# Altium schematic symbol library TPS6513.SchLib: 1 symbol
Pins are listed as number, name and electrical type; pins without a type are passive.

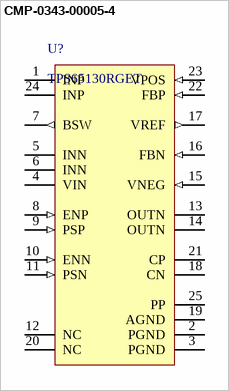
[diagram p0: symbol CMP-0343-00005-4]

## CMP-0343-00005-4
designator U?, comment TPS65130RGET
Boost Inverting Buck-Boost Voltage Converter with 2.7 to 5.5 V Input and -15 to 15 V Output, -40 to 85 degC, 24-Pin VQFN (RGE), Green (RoHS & no Sb/Br); Manufacturer: Texas Instruments; Vout2(V): -15 to -2; Regulated Outputs(#): 2; Vin(Max)(V): 5.5; Vout(Max)(V): 15; Topology: Boost, Inverting Buck-Boost; Switching Frequency(Typ)(kHz): 1400; SubFamily: Step-Up Regulator; Vin(Min)(V): 2.7
footprint RGE0024B_V (QFN, 24-Leads, Body 4x4mm, Pitch 0.5mm, Thermal Pad 2.45x2.45mm)
pins: 1 INP (power) "Boost converter switch input.", 2 PGND (power) "Power ground pin", 3 PGND (power) "Power ground pin", 4 VIN (power) "Control supply input", 5 INN (power) "Inverting converter switch input", 6 INN (power) "Inverting converter switch input", 7 BSW (out) "Gate control pin for external battery switch. This pin goes low when ENP is set high.", 8 ENP (in) "Enable pin for the positive output voltage (0 V: disabled, VIN: enabled)", 9 PSP (in) "Power-save mode enable for boost converter stage (0 V: disabled, VIN: enabled)", 10 ENN (in) "Enable pin for the negative output voltage (0 V: disabled, VIN: enabled)", 11 PSN (in) "Power-save mode enable for inverter stage (0 V: disabled, VIN: enabled)", 12 NC "Not connected", 13 OUTN (power) "Inverting converter switch output.", 14 OUTN (power) "Inverting converter switch output.", 15 VNEG (in) "Negative output voltage sense input", 16 FBN (in) "Feedback pin for the negative output voltage divider", 17 VREF (out) "Reference output voltage. Bypass this pin with a 220-nF capacitor to ground. Connect the lower resistor of the negative output voltage divider to this pin", 18 CN "Compensation pin for inverting converter control", 19 AGND (power) "Analog ground pin", 20 NC "Not connected", 21 CP "Compensation pin for boost converter control", 22 FBP (in) "Feedback pin for the positive output voltage divider", 23 VPOS (in) "Positive output voltage sense input", 24 INP (power) "Boost converter switch input.", 25 PP (power) "Must be soldered to achieve appropriate power dissipation and for mechanical reasons. Must be connected to GND."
